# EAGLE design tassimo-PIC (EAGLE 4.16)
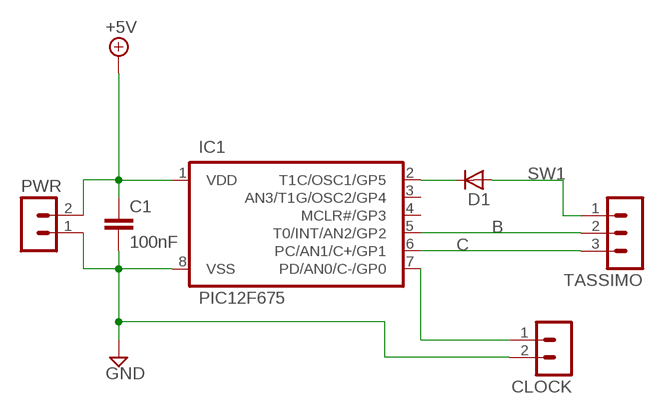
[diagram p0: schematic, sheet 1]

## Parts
C1  100nF  C2  [C2]
CLOCK  MA02-1  [MA02-1]
D1  1N400XR3  [D400X_R3]
IC1  PIC12F675  [DIL8]
PWR  MA02-1  [MA02-1]
TASSIMO  MA03-1  [MA03-1]

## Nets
+5V: C1.2 IC1.1(VDD) PWR.2
B: IC1.5(T0/INT/AN2/GP2) TASSIMO.2
C: IC1.6(PC/AN1/C+/GP1) TASSIMO.3
GND: C1.1 CLOCK.2 IC1.8(VSS) PWR.1
N$2: CLOCK.1 IC1.7(PD/AN0/C-/GP0)
N$3: D1.K(C) IC1.2(T1C/OSC1/GP5)
SW1: D1.A TASSIMO.1
Unconnected: IC1.3(AN3/T1G/OSC2/GP4) IC1.4(MCLR#/GP3)

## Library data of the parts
C1 = atrox-simple:C: keramik oder vielschicht Kondensator
CLOCK PWR = atrox-con-stift:MA02-1
D1 = atrox-simple:1N400X
IC1 = atrox-ic:PIC12F675
TASSIMO = atrox-con-stift:MA03-1: PIN HEADER

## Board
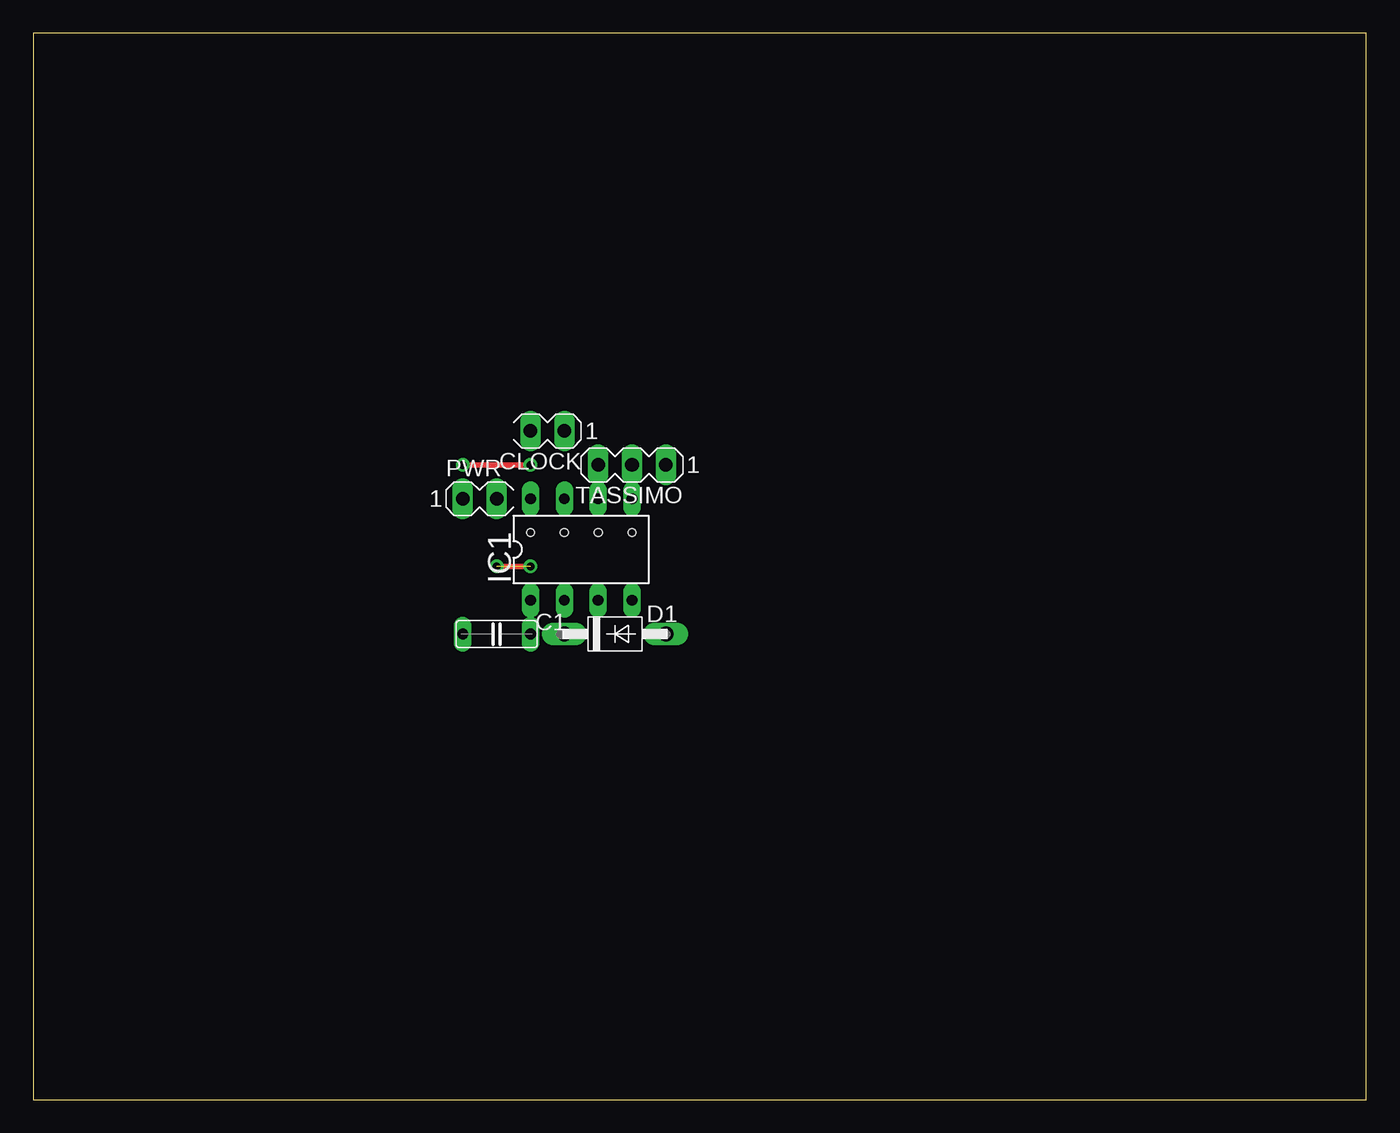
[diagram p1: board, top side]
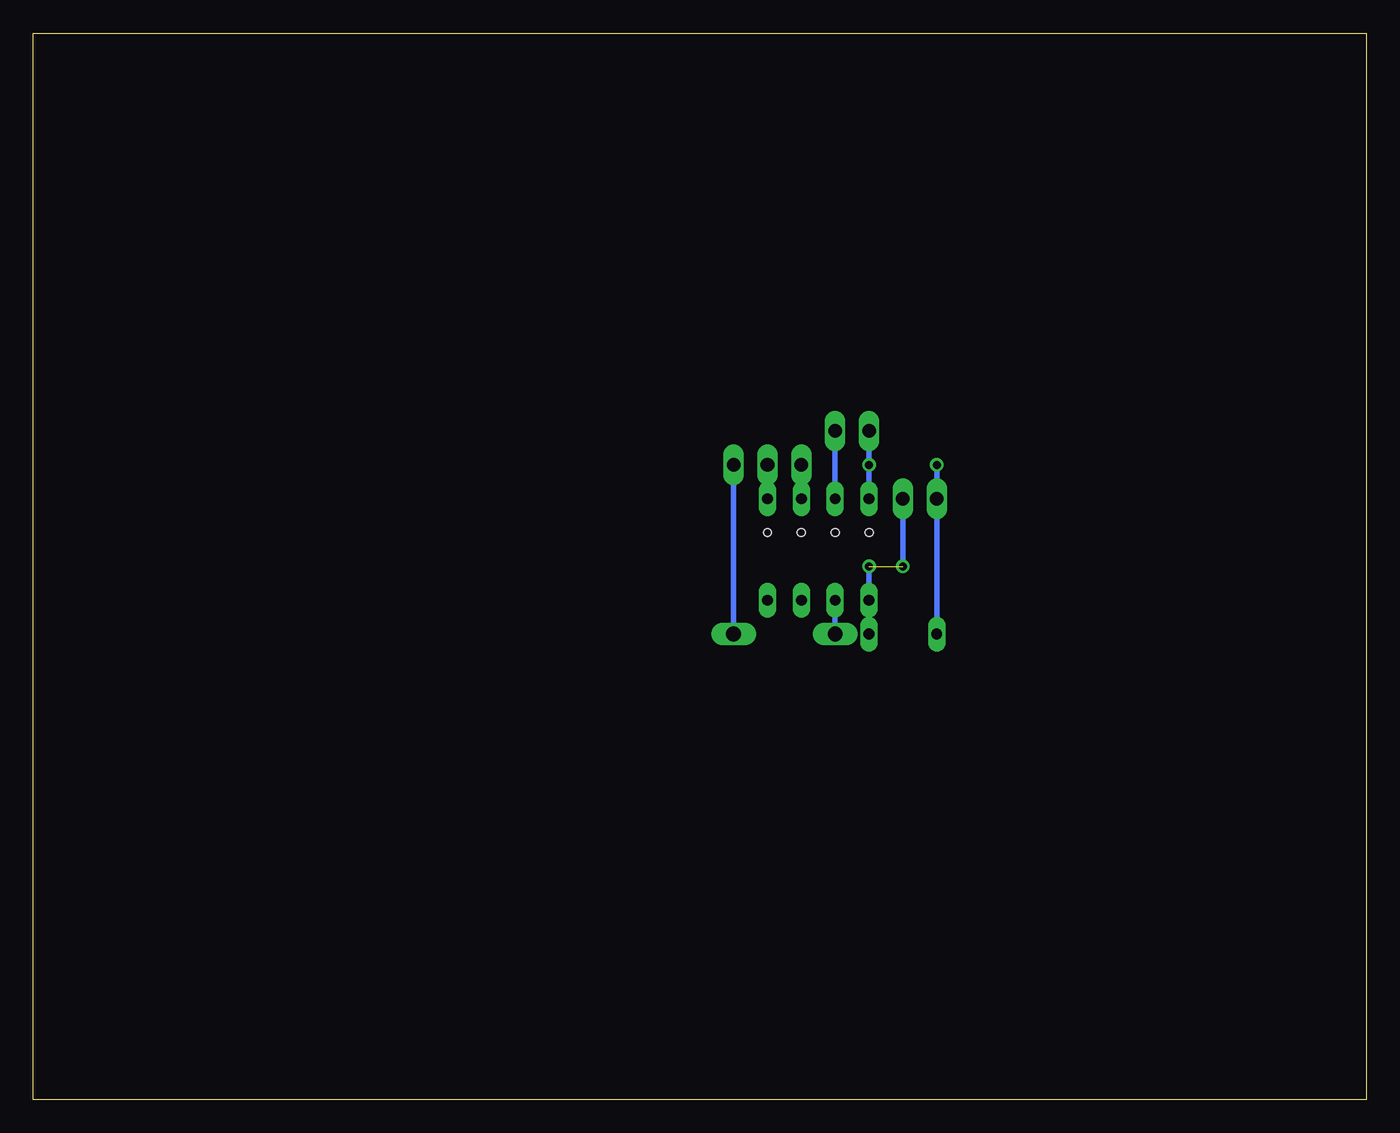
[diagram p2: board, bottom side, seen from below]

Size 100 x 80 mm. Coordinates in mm from the lower left corner, seen from the top.
Outline: 0,0 100,0 100,80 0,80 0,0
Copper layers (1*16): Top 0.035mm / dielectric 1.5mm / Bottom 0.035mm
Design rules "default": minimum track width 10mil, minimum drill 24mil, track to track 8mil, track to pad 8mil, pad to pad 8mil, via to via 8mil, smd to smd 8mil, copper to edge 40mil, drill to drill 8mil, minimum pad ring 10mil, minimum via ring 8mil, stop-mask expansion 4mil, vias tented up to drill 0mil, thermal gap 10mil
Holes 0.6 mm at 44.92,42.54 42.38,42.54 39.84,42.54 37.3,42.54

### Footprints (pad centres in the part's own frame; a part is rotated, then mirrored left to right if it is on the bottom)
C2 = drill 0.813 pad 1.143 long: 1 -2.54,0; 2 2.54,0
MA02-1 = drill 1.016 long: 1 -2.54,0; 2 0,0
D400X_R3 = drill 1.118 long: A 3.81,0; K -3.81,0
DIL8 = drill 0.813 long: 1 -3.81,-3.81; 2 -1.27,-3.81; 3 1.27,-3.81; 4 3.81,-3.81; 5 3.81,3.81; 6 1.27,3.81; 7 -1.27,3.81; 8 -3.81,3.81
MA03-1 = drill 1.016 long: 1 -2.54,0; 2 0,0; 3 2.54,0

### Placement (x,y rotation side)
C1  34.76,34.92 0 top
CLOCK  37.3,50.16 180 top
D1  43.65,34.92 0 top
IC1  41.11,41.27 0 top
PWR  34.76,45.08 0 top
TASSIMO  44.92,47.62 180 top

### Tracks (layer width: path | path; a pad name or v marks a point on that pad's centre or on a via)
+5V  (1 unrouted)
  Bottom 0.406: C1.2 IC1.1 37.3,40 | 34.76,40 PWR.2
B
  Bottom 0.406: TASSIMO.2 IC1.5
C
  Bottom 0.406: TASSIMO.3 IC1.6
GND  (via drill 0.6)
  Top 0.406: v32.22,47.62 v37.3,47.62
  Bottom 0.406: IC1.8 v37.3,47.62 CLOCK.2 | PWR.1 C1.1 v32.22,47.62
N$1  (via drill 0.6)
  Top 0.406: v34.76,40 v37.3,40
N$2
  Bottom 0.406: IC1.7 CLOCK.1
N$3
  Bottom 0.406: D1.K IC1.2
SW1  (via drill 0.6)
  Bottom 0.406: D1.A TASSIMO.1
  other vias: 47.46,47.62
